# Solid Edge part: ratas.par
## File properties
Title: ratas
Author: Stella-Marii
Template: Iso Metric Part.par
Last saved by: Stella-Marii
Revision: 6
Application: Solid Edge
Document Number: 36
Density: 7833,000 kg/m^3
Accuracy: 0,990
Username: Stella-Marii
Material: Steel, structural
Face Style: Steel
Fill Style: ANSI32(Steel)
Virtual Style: Brushed steel
Grouping: Metals\Steel
LibraryName: Materials
Coef. of Thermal Exp: 1.3e-05
Thermal Conductivity: 32.0
Specific Heat: 481.0
Modulus of Elasticity: 199947953000.0
Poisson's Ratio: 0.29
Yield Stress: 262000766.0
Ultimate Stress: 358527364.0
Elongation: 0.0
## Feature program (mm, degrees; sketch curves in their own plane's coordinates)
sketch for "unnamed RevolvedProtrusion 1" plane through (0, 0, 0) normal (0, -1, 0) x-axis (1, 0, 0)
  line (0, 20) -> (22.1468, 20)
  arc centre (22.1468, 58.3216) radius 38.3216 from (22.1468, 20) to (41.0734, 25) ccw
  arc centre (60, -8.3216) radius 38.3216 from (41.0734, 25) to (60, 30) cw
  line (60, 30) -> (70, 30)
  line (70, 29) -> (70, 30)
  line (70, 29) -> (65, 29)
  line (65, 29) -> (65, 24)
  line (65, 24) -> (70, 24)
  line (70, 24) -> (70, -24)
  line (70, -24) -> (65, -24)
  line (65, -24) -> (65, -29)
  line (65, -29) -> (70, -29)
  line (70, -29) -> (70, -30)
  line (70, -30) -> (60, -30)
  arc centre (60, 8.3216) radius 38.3216 from (41.0734, -25) to (60, -30) ccw
  arc centre (22.1468, -58.3216) radius 38.3216 from (22.1468, -20) to (41.0734, -25) cw
  line (22.1468, -20) -> (0, -20)
  line (0, -20) -> (0, 20)
  dimension (linear) = 65
  dimension (linear) = 60
  dimension (linear) = 60
  dimension (linear) = 70
  dimension (linear) = 70
  dimension (linear) = 65
revolve "unnamed RevolvedProtrusion 1" add full turn 360 deg
sketch for "unnamed Cutout 1" plane through (0, 0, 20) normal (0, 0, 1) x-axis (1, 0, 0)
  circle centre (0, 0) radius 5
extrude "unnamed Cutout 1" cut finite 277.9423 symmetric
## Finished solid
Body 1: solid body, 18 faces, 18 edges, 0 vertices.
  Faces by surface: plane 8, cylinder 6, torus 4
  Edges by curve: circle 18
Bounding box of the edges (mm; curved faces can reach further): 140.000 x 140.000 x 60.000, from (-70, -70, -30) to (70, 70, 30).
Cylindrical faces by radius (mm): R5 x1, R65 x2, R70 x3
Toroidal faces (ring radius, tube radius in mm): R22.1468 r38.3216 x2, R60 r38.3216 x2
Planar faces by outward normal: +z 4, -z 4
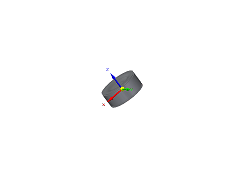
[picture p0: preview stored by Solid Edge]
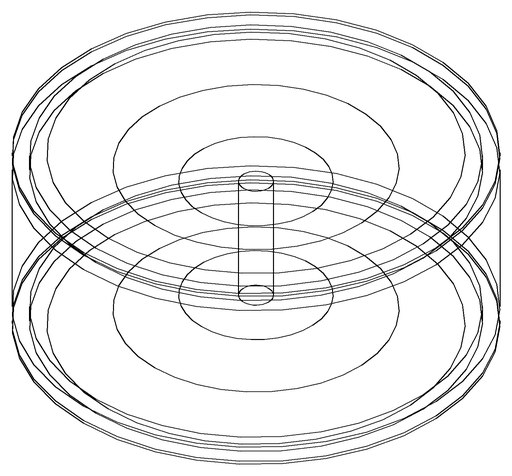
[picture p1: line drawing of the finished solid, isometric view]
